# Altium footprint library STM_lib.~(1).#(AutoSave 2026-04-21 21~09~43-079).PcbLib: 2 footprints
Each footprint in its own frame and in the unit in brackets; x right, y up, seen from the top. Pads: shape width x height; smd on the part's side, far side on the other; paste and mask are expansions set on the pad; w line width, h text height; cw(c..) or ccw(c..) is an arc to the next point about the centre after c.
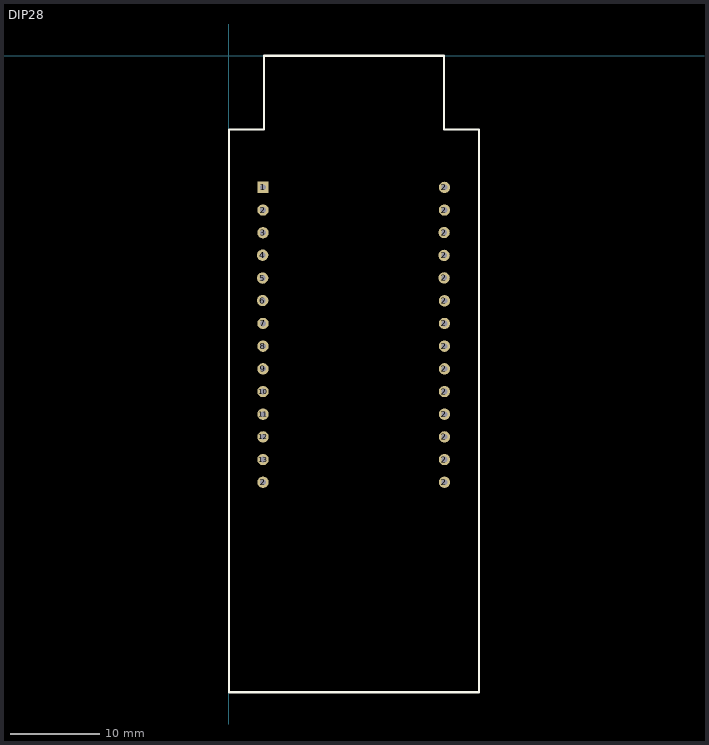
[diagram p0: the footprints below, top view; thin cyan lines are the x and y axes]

## DIP28 [mil]
pads (28):
  rect 50x50 hole 25: 1(150,-580)
  round 50 hole 25: 2(150,-1880) 2(150,-680) 2(948.51,-979.05) 2(948.51,-879.9) 2(948.51,-779.04) 2(950,-1880) 2(950,-1780) 2(950,-1680) 2(950,-1580) 2(950,-1480) 2(950,-1380) 2(950,-1280) 2(950,-1180) 2(950,-1080) 2(950,-680) 2(950,-580) 3(150,-780) 4(148.51,-879.04) 5(148.51,-979.9) 6(148.51,-1079.05) 7(150,-1180) 8(150,-1280) 9(150,-1380) 10(150,-1480) 11(150,-1580) 12(150,-1680) 13(150,-1780)
Top Overlay:
  lines w10: 0,-2805.51 1102.36,-2805.51 1102.36,-325.2 947.56,-325.2 947.56,0 154.8,0 154.8,-325.2 0,-325.2 0,-2805.51

## PCBComponent_1 [mil]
